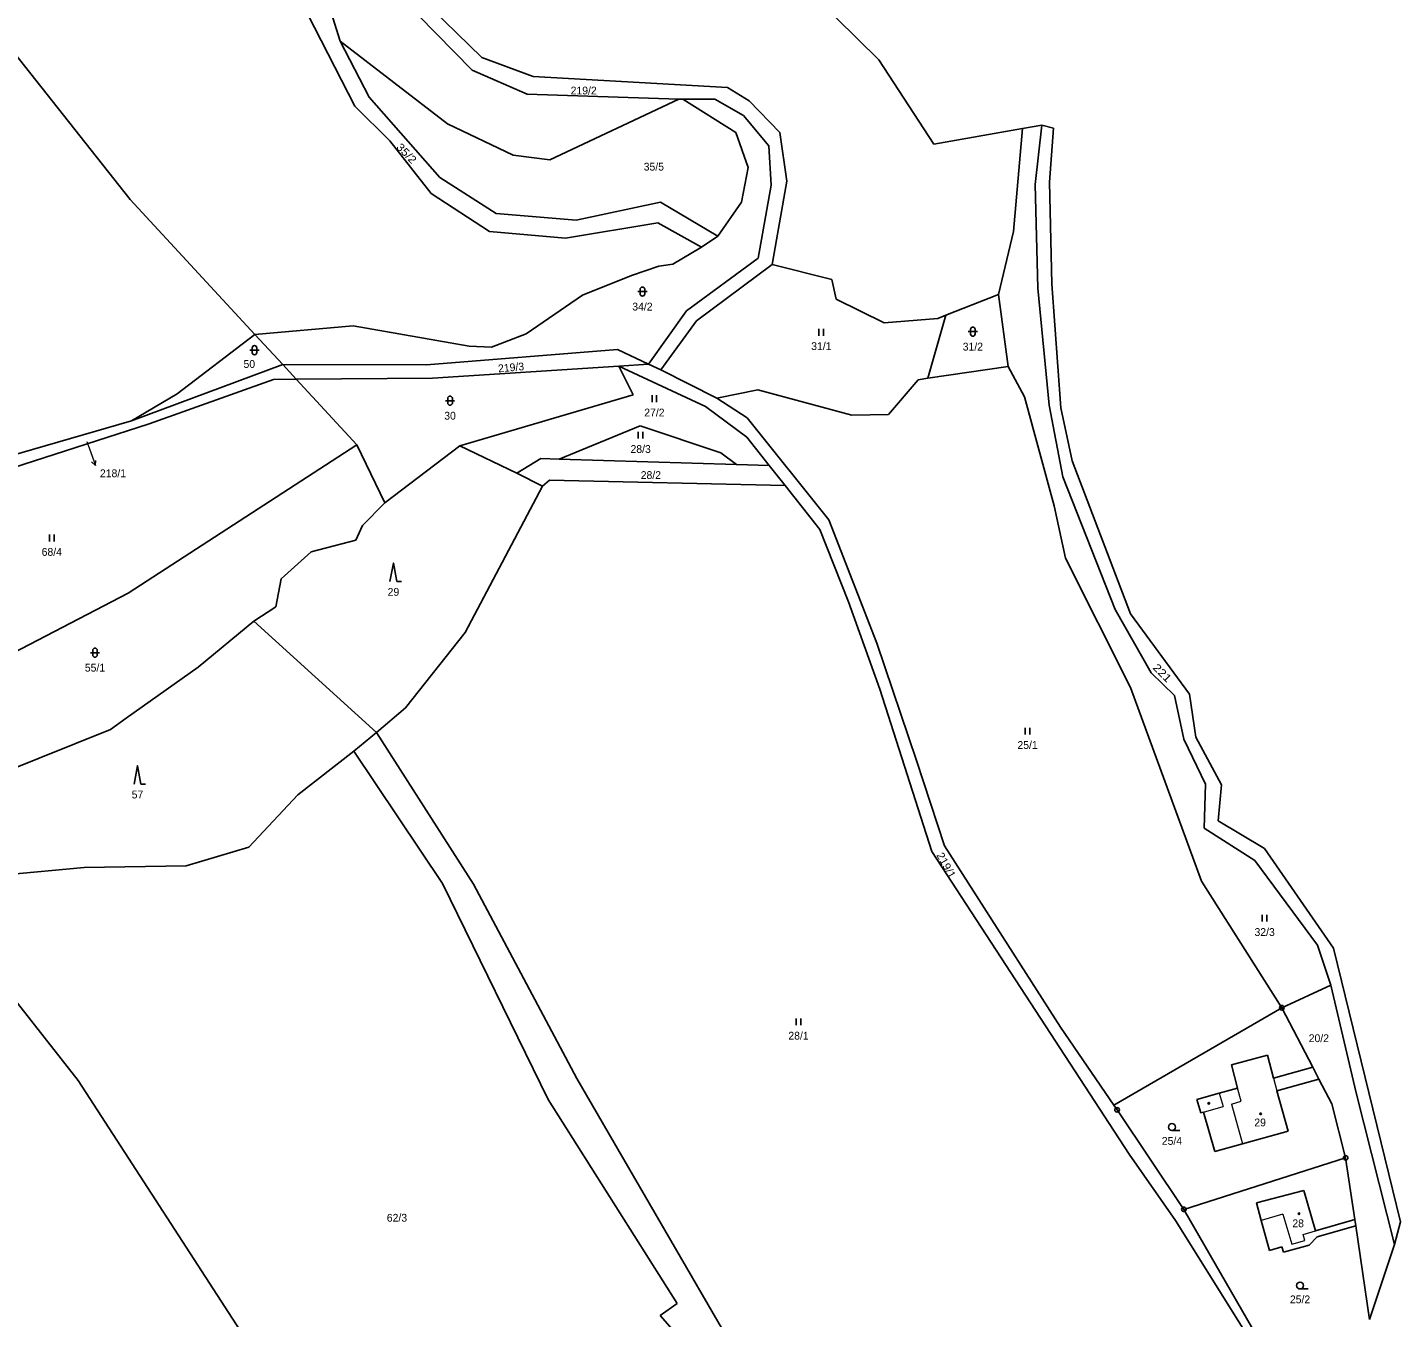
# Model space of a CAD drawing. Extents: x -601877 to -599786, y -1122905 to -1121218.
# Drawn here: x -600177.9 to -599878.4, y -1121972.1 to -1121690.7 of the extents above; entities that cross this region are included whole.
import ezdxf
from ezdxf.enums import TextEntityAlignment as Align

# ---------------------------------------------------------------- set-up
doc = ezdxf.new("R2010")
doc.units = 0
doc.header["$LTSCALE"] = 0.68
for name, color, linetype, lineweight in [('1', 7, 'Continuous', 25), ('3', 7, 'Continuous', 25), ('4', 7, 'Continuous', 13), ('5', 7, 'Continuous', 25), ('7', 7, 'Continuous', 13), ('8', 7, 'Continuous', 25)]:
    doc.layers.add(name, color=color, linetype=linetype, lineweight=lineweight)
doc.layers.add('2', color=7, linetype='Continuous')

msp = doc.modelspace()

# ---------------------------------------------------------------- linework, layer by layer
at = {"layer": '1'}
for p, q in [((-600013.81, -1121676.4), (-599992.21, -1121697.77)), ((-600080.86, -1121700.01), (-600101.76, -1121678.76)), ((-600098.79, -1121677.77), (-600078.77, -1121697.25)), ((-600116.75, -1121687.93), (-600106.45, -1121707.88)), ((-600184.91, -1121691.09), (-600155.44, -1121728.29)), ((-600109.68, -1121693.73), (-600111.25, -1121688.66)), ((-600109.68, -1121693.73), (-600103.33, -1121705.92)), ((-600086.25, -1121711.78), (-600109.68, -1121693.73)), ((-600078.77, -1121697.25), (-600067.55, -1121701.44)), ((-600068.87, -1121705.29), (-600080.86, -1121700.01)), ((-599992.21, -1121697.77), (-599980.21, -1121716.19)), ((-600067.55, -1121701.44), (-600025.21, -1121703.86)), ((-600103.33, -1121705.92), (-600087.96, -1121723.47)), ((-600068.87, -1121705.29), (-600035.81, -1121706.35)), ((-600035.81, -1121706.35), (-600063.92, -1121719.6)), ((-600035.81, -1121706.35), (-600034.96, -1121706.38)), ((-600034.96, -1121706.38), (-600027.96, -1121706.39)), ((-600023.34, -1121713.65), (-600034.96, -1121706.38)), ((-600027.96, -1121706.39), (-600021.69, -1121709.91)), ((-600025.21, -1121703.86), (-600020.48, -1121706.72)), ((-600106.45, -1121707.88), (-600098.84, -1121715.49)), ((-600020.48, -1121706.72), (-600013.77, -1121713.65)), ((-600071.95, -1121718.61), (-600086.25, -1121711.78)), ((-600021.69, -1121709.91), (-600016.19, -1121716.52)), ((-599960.83, -1121712.78), (-599956.66, -1121712.04)), ((-599956.66, -1121712.04), (-599958.05, -1121724.97)), ((-599954.1, -1121712.73), (-599956.66, -1121712.04)), ((-600020.7, -1121721.25), (-600023.34, -1121713.65)), ((-600013.77, -1121713.65), (-600012.23, -1121724.22)), ((-599980.21, -1121716.19), (-599960.83, -1121712.78)), ((-599962.81, -1121735.23), (-599960.83, -1121712.78)), ((-599954.97, -1121724.45), (-599954.1, -1121712.73)), ((-600098.84, -1121715.49), (-600089.84, -1121726.96)), ((-600016.19, -1121716.52), (-600015.64, -1121725.1)), ((-600063.92, -1121719.6), (-600071.95, -1121718.61)), ((-600022.13, -1121728.84), (-600020.7, -1121721.25)), ((-600087.96, -1121723.47), (-600075.63, -1121731.31)), ((-600012.23, -1121724.22), (-600015.47, -1121742.46)), ((-600089.84, -1121726.96), (-600077.08, -1121735.23)), ((-600015.64, -1121725.1), (-600018.5, -1121741.06)), ((-599958.05, -1121724.97), (-599957.47, -1121747.62)), ((-599954.41, -1121746.62), (-599954.97, -1121724.45)), ((-600155.44, -1121728.29), (-600128.28, -1121757.67)), ((-600058.22, -1121732.76), (-600039.8, -1121728.84)), ((-600039.8, -1121728.84), (-600027.3, -1121736.22)), ((-600027.3, -1121736.22), (-600022.13, -1121728.84)), ((-600075.63, -1121731.31), (-600058.22, -1121732.76)), ((-600060.54, -1121736.68), (-600040.38, -1121733.34)), ((-600040.38, -1121733.34), (-600030.82, -1121738.66)), ((-600077.08, -1121735.23), (-600060.54, -1121736.68)), ((-599966.09, -1121748.96), (-599962.81, -1121735.23)), ((-600040.17, -1121742.82), (-600037.09, -1121742.38)), ((-600018.5, -1121741.06), (-600034.12, -1121752.51)), ((-600056.78, -1121749.09), (-600046.11, -1121744.8)), ((-600046.11, -1121744.8), (-600040.17, -1121742.82)), ((-600031.92, -1121754.73), (-600015.47, -1121742.46)), ((-600015.47, -1121742.46), (-600002.44, -1121745.71)), ((-600002.44, -1121745.71), (-600001.51, -1121750)), ((-599957.47, -1121747.62), (-599955.01, -1121773.14)), ((-599952.46, -1121773.73), (-599954.41, -1121746.62)), ((-600069.09, -1121757.57), (-600056.78, -1121749.09)), ((-600001.51, -1121750), (-599991, -1121755.18)), ((-599977.59, -1121753.51), (-599966.09, -1121748.96)), ((-599966.09, -1121748.96), (-599964, -1121764.7)), ((-600034.12, -1121752.51), (-600042.4, -1121764.19)), ((-599991, -1121755.18), (-599979.29, -1121754.18)), ((-599977.59, -1121753.51), (-599981.49, -1121767.26)), ((-599979.29, -1121754.18), (-599977.59, -1121753.51)), ((-600128.28, -1121757.67), (-600106.82, -1121755.81)), ((-600106.82, -1121755.81), (-600081.52, -1121760.21)), ((-600039.75, -1121765.44), (-600031.92, -1121754.73)), ((-600128.28, -1121757.67), (-600145.23, -1121770.61)), ((-600122.19, -1121764.27), (-600128.28, -1121757.67)), ((-600081.52, -1121760.21), (-600076.68, -1121760.43)), ((-600076.68, -1121760.43), (-600069.09, -1121757.57)), ((-600049.19, -1121760.98), (-600090.87, -1121764.28)), ((-600042.4, -1121764.19), (-600049.19, -1121760.98)), ((-600122.19, -1121764.27), (-600155.16, -1121776.54)), ((-600090.87, -1121764.28), (-600122.19, -1121764.27)), ((-600119.24, -1121767.47), (-600122.19, -1121764.27)), ((-600089.55, -1121767.24), (-600048.86, -1121764.61)), ((-600048.86, -1121764.61), (-600042.4, -1121764.19)), ((-600048.86, -1121764.61), (-600029.99, -1121773.39)), ((-600048.86, -1121764.61), (-600045.78, -1121770.89)), ((-600039.75, -1121765.44), (-600042.4, -1121764.19)), ((-600039.75, -1121765.44), (-600027.49, -1121771.55)), ((-599964, -1121764.7), (-599981.49, -1121767.26)), ((-599964, -1121764.7), (-599960.4, -1121771.29)), ((-600151.33, -1121777.18), (-600124.18, -1121767.51)), ((-600124.18, -1121767.51), (-600119.24, -1121767.47)), ((-600119.24, -1121767.47), (-600089.55, -1121767.24)), ((-600106.05, -1121781.78), (-600119.24, -1121767.47)), ((-599983.58, -1121767.56), (-599990.07, -1121775.15)), ((-599981.49, -1121767.26), (-599983.58, -1121767.56)), ((-600145.23, -1121770.61), (-600155.16, -1121776.54)), ((-600045.78, -1121770.89), (-600083.58, -1121781.98)), ((-600018.55, -1121769.76), (-600027.49, -1121771.55)), ((-600027.49, -1121771.55), (-600020.89, -1121775.91)), ((-599998.1, -1121775.26), (-600018.55, -1121769.76)), ((-599960.4, -1121771.29), (-599953.91, -1121795.06)), ((-600029.99, -1121773.39), (-600020.97, -1121780.1)), ((-599990.07, -1121775.15), (-599998.1, -1121775.26)), ((-599952.06, -1121788.74), (-599955.01, -1121773.14)), ((-599950.04, -1121785.23), (-599952.46, -1121773.73)), ((-600155.16, -1121776.54), (-600187.23, -1121785.84)), ((-600181.08, -1121786.75), (-600151.33, -1121777.18)), ((-600061.88, -1121784.87), (-600044.24, -1121777.6)), ((-600044.24, -1121777.6), (-600026.64, -1121783.54)), ((-600020.89, -1121775.91), (-600003.07, -1121798.14)), ((-600020.97, -1121780.1), (-600016.1, -1121786.26)), ((-600155.89, -1121814.11), (-600106.05, -1121781.78)), ((-600106.05, -1121781.78), (-600099.92, -1121794.4)), ((-600099.92, -1121794.4), (-600083.58, -1121781.98)), ((-600083.58, -1121781.98), (-600071.13, -1121787.92)), ((-600026.64, -1121783.54), (-600023.23, -1121786.04)), ((-600071.13, -1121787.92), (-600065.9, -1121784.75)), ((-600065.9, -1121784.75), (-600061.88, -1121784.87)), ((-600061.88, -1121784.87), (-600023.23, -1121786.04)), ((-600023.23, -1121786.04), (-600016.1, -1121786.26)), ((-600016.1, -1121786.26), (-600012.64, -1121790.63)), ((-599937.32, -1121818.6), (-599950.04, -1121785.23)), ((-600071.13, -1121787.92), (-600065.56, -1121790.81)), ((-600065.56, -1121790.81), (-600064.03, -1121789.49)), ((-600064.03, -1121789.49), (-600012.64, -1121790.63)), ((-599940.65, -1121817.71), (-599952.06, -1121788.74)), ((-600065.56, -1121790.81), (-600082.38, -1121822.69)), ((-600012.64, -1121790.63), (-600005.03, -1121800.25)), ((-600104.81, -1121799.35), (-600099.92, -1121794.4)), ((-599953.91, -1121795.06), (-599951.49, -1121806.51)), ((-600003.07, -1121798.14), (-599992.62, -1121825)), ((-600106.25, -1121802.55), (-600104.81, -1121799.35)), ((-600005.03, -1121800.25), (-599998.76, -1121815.98)), ((-600122.5, -1121811.01), (-600115.98, -1121805.11)), ((-600115.98, -1121805.11), (-600106.25, -1121802.55)), ((-599951.49, -1121806.51), (-599937.3, -1121834.68)), ((-600123.66, -1121817.08), (-600122.5, -1121811.01)), ((-600220.66, -1121847.71), (-600155.89, -1121814.11)), ((-600128.47, -1121820.25), (-600123.66, -1121817.08)), ((-599998.76, -1121815.98), (-599991.94, -1121835.03)), ((-600140.61, -1121830.27), (-600128.47, -1121820.25)), ((-600128.47, -1121820.25), (-600101.75, -1121844.5)), ((-599932.77, -1121831.5), (-599940.65, -1121817.71)), ((-599924.4, -1121836.14), (-599937.32, -1121818.6)), ((-600082.38, -1121822.69), (-600095.42, -1121839.11)), ((-599992.62, -1121825), (-599983.94, -1121850.59)), ((-600156.31, -1121841.4), (-600140.61, -1121830.27)), ((-599927.68, -1121836.43), (-599932.77, -1121831.5)), ((-599991.94, -1121835.03), (-599980.61, -1121870.47)), ((-599937.3, -1121834.68), (-599921.79, -1121876.95)), ((-599925.63, -1121845.95), (-599927.68, -1121836.43)), ((-599923.01, -1121845.54), (-599924.4, -1121836.14)), ((-600095.42, -1121839.11), (-600101.75, -1121844.5)), ((-600183.13, -1121853.27), (-600159.75, -1121843.89)), ((-600159.75, -1121843.89), (-600156.31, -1121841.4)), ((-600101.75, -1121844.5), (-600106.65, -1121848.57)), ((-600101.75, -1121844.5), (-600080.56, -1121877.59)), ((-599920.95, -1121855.8), (-599925.63, -1121845.95)), ((-599917.43, -1121855.94), (-599923.01, -1121845.54)), ((-600106.65, -1121848.57), (-600118.9, -1121858.1)), ((-600106.65, -1121848.57), (-600087.38, -1121877.48)), ((-599983.94, -1121850.59), (-599977.89, -1121869.24)), ((-599921.2, -1121865.4), (-599920.95, -1121855.8)), ((-599918.2, -1121863.8), (-599917.43, -1121855.94)), ((-600118.9, -1121858.1), (-600129.6, -1121869.55)), ((-599908.04, -1121869.84), (-599918.2, -1121863.8)), ((-599910.2, -1121872.46), (-599921.2, -1121865.4)), ((-600129.6, -1121869.55), (-600143.24, -1121873.61)), ((-599937.6, -1121936.5), (-599980.61, -1121870.47)), ((-599977.89, -1121869.24), (-599952.59, -1121908.81)), ((-599908.04, -1121869.84), (-599892.99, -1121891.55)), ((-600165.5, -1121873.94), (-600182.73, -1121875.57)), ((-600143.24, -1121873.61), (-600165.5, -1121873.94)), ((-599896.5, -1121890.92), (-599910.2, -1121872.46)), ((-599921.79, -1121876.95), (-599904.27, -1121904.54)), ((-600087.38, -1121877.48), (-600064.28, -1121924.59)), ((-600080.56, -1121877.59), (-600058.01, -1121919.97)), ((-600194.67, -1121885.03), (-600166.79, -1121920.41)), ((-599893.62, -1121899.62), (-599896.5, -1121890.92)), ((-599892.99, -1121891.55), (-599878.39, -1121951.24)), ((-599904.27, -1121904.54), (-599893.62, -1121899.62)), ((-599888.04, -1121923.1), (-599893.62, -1121899.62)), ((-599940.92, -1121925.76), (-599904.27, -1121904.54)), ((-599904.27, -1121904.54), (-599897.55, -1121917.5)), ((-599952.59, -1121908.81), (-599940.92, -1121925.76)), ((-599915.27, -1121916.98), (-599907.44, -1121914.9)), ((-599907.44, -1121914.9), (-599906.13, -1121919.89)), ((-599913.92, -1121922.07), (-599915.27, -1121916.98)), ((-599906.13, -1121919.89), (-599897.55, -1121917.5)), ((-599897.55, -1121917.5), (-599896.18, -1121920.13)), ((-600166.79, -1121920.41), (-600120.82, -1121991.29)), ((-600058.01, -1121919.97), (-600018.09, -1121988.87)), ((-599917.92, -1121923.18), (-599913.92, -1121922.07)), ((-599905.39, -1121922.7), (-599896.18, -1121920.13)), ((-599896.18, -1121920.13), (-599893.38, -1121925.53)), ((-600064.28, -1121924.59), (-600036.13, -1121969.06)), ((-599922.82, -1121924.55), (-599917.92, -1121923.18)), ((-599922.82, -1121924.55), (-599921.97, -1121927.5)), ((-599905.39, -1121922.7), (-599902.93, -1121931.5)), ((-599879.68, -1121956.15), (-599888.04, -1121923.1)), ((-599940.22, -1121926.82), (-599940.92, -1121925.76)), ((-599925.64, -1121948.52), (-599940.22, -1121926.82)), ((-599921.97, -1121927.5), (-599921.39, -1121927.33)), ((-599918.92, -1121935.88), (-599921.39, -1121927.33)), ((-599890.36, -1121937.29), (-599893.38, -1121925.53)), ((-599902.93, -1121931.5), (-599912.89, -1121934.23)), ((-599937.6, -1121936.5), (-599927.48, -1121950.92)), ((-599912.89, -1121934.23), (-599918.92, -1121935.88)), ((-599890.36, -1121937.29), (-599925.64, -1121948.52)), ((-599890.36, -1121937.29), (-599888.38, -1121950.7)), ((-599899.51, -1121944.38), (-599909.84, -1121947.09)), ((-599899.51, -1121944.38), (-599896.95, -1121953.19)), ((-599925.64, -1121948.52), (-599908.41, -1121978.43)), ((-599909.84, -1121947.09), (-599908.77, -1121950.92)), ((-599927.48, -1121950.92), (-599911.32, -1121976.79)), ((-599906.94, -1121957.47), (-599908.77, -1121950.92)), ((-599896.95, -1121953.19), (-599888.38, -1121950.7)), ((-599888.38, -1121950.7), (-599888.17, -1121952.09)), ((-599879.68, -1121956.15), (-599878.39, -1121951.24)), ((-599898.34, -1121956.31), (-599896.56, -1121954.53)), ((-599896.56, -1121954.53), (-599888.17, -1121952.09)), ((-599888.17, -1121952.09), (-599885.16, -1121972.53)), ((-599904.25, -1121956.72), (-599906.94, -1121957.47)), ((-599903.92, -1121957.87), (-599904.25, -1121956.72)), ((-599898.34, -1121956.31), (-599903.92, -1121957.87)), ((-599879.68, -1121956.15), (-599885.16, -1121972.53)), ((-600036.13, -1121969.06), (-600039.86, -1121971.7)), ((-600039.86, -1121971.7), (-600013.69, -1122001.41))]:
    msp.add_line(p, q, dxfattribs=at)
msp.add_lwpolyline([(-600037.09, -1121742.38), (-600030.82, -1121738.66), (-600027.3, -1121736.22)], dxfattribs=at)
at = {"layer": '3'}
for p, q in [((-600044.741, -1121748.341), (-600042.739, -1121748.341)), ((-600044.241, -1121747.841), (-600044.241, -1121748.842)), ((-600043.239, -1121748.842), (-600043.239, -1121747.841)), ((-600005.231, -1121757.96), (-600005.231, -1121756.46)), ((-600004.23, -1121757.96), (-600004.23, -1121756.46)), ((-599972.671, -1121757.071), (-599970.669, -1121757.071)), ((-599972.171, -1121756.571), (-599972.171, -1121757.572)), ((-599971.169, -1121757.572), (-599971.169, -1121756.571)), ((-600129.361, -1121761.121), (-600127.359, -1121761.121)), ((-600128.861, -1121760.621), (-600128.861, -1121761.622)), ((-600127.859, -1121761.622), (-600127.859, -1121760.621)), ((-600086.701, -1121772.141), (-600084.699, -1121772.141)), ((-600086.201, -1121771.641), (-600086.201, -1121772.642)), ((-600085.199, -1121772.642), (-600085.199, -1121771.641)), ((-600041.641, -1121772.44), (-600041.641, -1121770.94)), ((-600040.64, -1121772.44), (-600040.64, -1121770.94)), ((-600044.641, -1121780.4), (-600044.641, -1121778.9)), ((-600043.64, -1121780.4), (-600043.64, -1121778.9)), ((-600173.071, -1121802.85), (-600173.071, -1121801.35)), ((-600172.07, -1121802.85), (-600172.07, -1121801.35)), ((-600097.3, -1121811.56), (-600096.304, -1121811.56)), ((-600164.141, -1121827.101), (-600162.139, -1121827.101)), ((-600163.641, -1121826.601), (-600163.641, -1121827.602)), ((-600162.639, -1121827.602), (-600162.639, -1121826.601)), ((-599960.251, -1121844.97), (-599960.251, -1121843.47)), ((-599959.25, -1121844.97), (-599959.25, -1121843.47)), ((-600153.12, -1121855.76), (-600152.124, -1121855.76)), ((-599908.541, -1121885.76), (-599908.541, -1121884.26)), ((-599907.54, -1121885.76), (-599907.54, -1121884.26)), ((-600010.211, -1121908.37), (-600010.211, -1121906.87)), ((-600009.21, -1121908.37), (-600009.21, -1121906.87)), ((-599928.243, -1121931.32), (-599926.493, -1121931.32)), ((-599900.303, -1121965.88), (-599898.553, -1121965.88))]:
    msp.add_line(p, q, dxfattribs=at)
for points in [[(-600097.3, -1121811.56), (-600098.05, -1121807.56), (-600098.8, -1121811.56)], [(-600153.12, -1121855.76), (-600153.87, -1121851.76), (-600154.62, -1121855.76)]]:
    msp.add_lwpolyline(points, dxfattribs=at)
for centre in [(-599928.2429, -1121930.5698), (-599900.3029, -1121965.1298)]:
    msp.add_circle(centre, 0.75, dxfattribs=at)
for centre, start, end in [((-600043.74, -1121747.8409), 0, 180), ((-600043.74, -1121748.8409), 180, 359.98789), ((-599971.67, -1121756.5709), 0, 180), ((-600128.36, -1121760.6209), 0, 180), ((-599971.67, -1121757.5709), 180, 359.98789), ((-600128.36, -1121761.6209), 180, 359.98789), ((-600085.7, -1121771.6409), 0, 180), ((-600085.7, -1121772.6409), 180, 359.98789), ((-600163.14, -1121826.6009), 0, 180), ((-600163.14, -1121827.6009), 180, 359.98789)]:
    msp.add_arc(centre, 0.5, start, end, dxfattribs=at)
at = {"layer": '4'}
for p, q in [((-599906.13, -1121919.89), (-599905.39, -1121922.7)), ((-599917.92, -1121923.18), (-599917.08, -1121926.07)), ((-599921.39, -1121927.33), (-599917.08, -1121926.07)), ((-599915.27, -1121925.56), (-599912.89, -1121934.23)), ((-599904.04, -1121949.6), (-599908.77, -1121950.92)), ((-599899.64, -1121953.97), (-599896.95, -1121953.19)), ((-599899.25, -1121955.31), (-599899.64, -1121953.97))]:
    msp.add_line(p, q, dxfattribs=at)
for points in [[(-599915.27, -1121925.56), (-599913.15, -1121924.95), (-599913.92, -1121922.07)], [(-599904.04, -1121949.6), (-599902.11, -1121956.14), (-599899.25, -1121955.31)]]:
    msp.add_lwpolyline(points, dxfattribs=at)
at = {"layer": '5'}
for centre in [(-599920.2168, -1121925.4092), (-599908.9168, -1121927.6792), (-599900.5368, -1121949.4792)]:
    msp.add_circle(centre, 0.175, dxfattribs=at)
at = {"layer": '7'}
msp.add_line((-600163.054, -1121786.26), (-600162.926, -1121785.148), dxfattribs=at)
msp.add_lwpolyline([(-600164.95, -1121781.03), (-600164.08, -1121783.44), (-600163.054, -1121786.26), (-600163.867, -1121785.49)], dxfattribs=at)
at = {"layer": '8'}
for centre, radius in [((-599904.27, -1121904.5399), 0.5), ((-599904.27, -1121904.5399), 0.0303), ((-599940.22, -1121926.8199), 0.5), ((-599940.22, -1121926.8199), 0.0303), ((-599890.36, -1121937.2899), 0.5), ((-599890.36, -1121937.2899), 0.0303), ((-599925.64, -1121948.5199), 0.5), ((-599925.64, -1121948.5199), 0.0303)]:
    msp.add_circle(centre, radius, dxfattribs=at)

# ---------------------------------------------------------------- texts
at = {"layer": '2'}
for s, p in [('219/2', (-600056.55, -1121705.335)), ('35/5', (-600041.249, -1121721.945)), ('34/2', (-600043.739, -1121752.465)), ('31/1', (-600004.719, -1121761.085)), ('31/2', (-599971.669, -1121761.195)), ('50', (-600129.479, -1121764.985)), ('30', (-600085.699, -1121776.265)), ('27/2', (-600041.129, -1121775.565)), ('28/3', (-600044.129, -1121783.525)), ('28/2', (-600041.899, -1121789.215)), ('68/4', (-600172.559, -1121805.975)), ('29', (-600098.049, -1121814.685)), ('55/1', (-600163.139, -1121831.225)), ('25/1', (-599959.739, -1121848.095)), ('57', (-600153.869, -1121858.885)), ('32/3', (-599908.029, -1121888.885)), ('28/1', (-600009.699, -1121911.495)), ('20/2', (-599896.209, -1121912.035)), ('29', (-599909.019, -1121930.415)), ('25/4', (-599928.249, -1121934.445)), ('62/3', (-600097.279, -1121951.205)), ('28', (-599900.719, -1121952.415)), ('25/2', (-599900.309, -1121969.005))]:
    msp.add_text(s, height=1.7, dxfattribs=at).set_placement(p, align=Align.CENTER)
for s, rotation, width, p in [('35/2', 314, 1.15, (-600095.8042, -1121718.7755)), ('221', 315, 1.2, (-599930.9535, -1121832.1065)), ('219/1', 299, 1.05, (-599978.2247, -1121873.8754))]:
    msp.add_text(s, height=1.7, rotation=rotation, dxfattribs=dict(at, width=width)).set_placement(p, align=Align.CENTER)
msp.add_text('219/3', height=1.7, rotation=5, dxfattribs=at).set_placement((-600072.3151, -1121765.7195), align=Align.CENTER)
msp.add_text('218/1', height=1.7, dxfattribs=at).set_placement((-600162.06, -1121788.825))

doc.saveas('drawing.dxf')
